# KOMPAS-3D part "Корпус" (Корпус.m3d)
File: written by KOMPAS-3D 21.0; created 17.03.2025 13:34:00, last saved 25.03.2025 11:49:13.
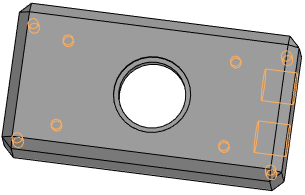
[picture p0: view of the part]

Document properties: Полное имя файла: C:\Производство\технологии\KazanTarget\эксперименты\Перспектива\Корпус платы перспективы\Корпус.m3d; Автор: fedorov478@gmail.com

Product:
- Part/product: Корпус
    Масса: 0.528769
    Форматы листов документа: A2

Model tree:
1. Эскиз:7
2. Элемент выдавливания:10
     Расстояние 1 = 106
3. Эскиз:8  (with: Элемент выдавливания:10)
4. Элемент выдавливания:11
     Расстояние 2 = 3
5. Эскиз:9  (with: Элемент выдавливания:10)
6. Отверстие:9  (with: Элемент выдавливания:10)  (labels: M4)
     Глубина выреза = 12; Диаметр отверстия = 3.24223; Угол конуса дна = 118; Расстояние 1 = 101
7. M4  (with: Элемент выдавливания:10)  (labels: M4; cil0_24705-2004 coarse)
     Длина резьбы = 10; Шаг резьбы = 0.7; Номинальный диаметр резьбы = 4
8. Фаска:3  (with: Отверстие:9)
     Угол = 45; Длина 1 = 1; Длина 2 = 1
9. Элемент выдавливания:13  (with: Элемент выдавливания:11)
     Расстояние 2 = 12
10. Массив по точкам:1
11. Экземпляр ( 2 )  (with: Отверстие:9, Эскиз:9)  (labels: M4)
12. Фаска:3
13. Экземпляр ( 1 )  (with: Отверстие:9, Эскиз:9)  (labels: M4)
14. Фаска:3
15. Экземпляр ( 3 )  (with: Отверстие:9, Эскиз:9)  (labels: M4)
16. Фаска:3
17. Эскиз:11  (with: Элемент выдавливания:13)
18. Эскиз:12  (with: Элемент выдавливания:10)
19. Отверстие:10  (with: Элемент выдавливания:10)  (labels: M12x1,5)
     Глубина выреза = 13; Диаметр отверстия = 10.3762; Угол конуса дна = 118; Расстояние 1 = 18; Расстояние 2 = 14
20. M12x1,5  (with: Элемент выдавливания:10)  (labels: M12x1,5; cil0_24705-2004 fine)
     Длина резьбы = 12; Шаг резьбы = 1.5; Номинальный диаметр резьбы = 12
21. Массив по точкам:2  (with: Экземпляр ( 1 ), Отверстие:10)  (labels: 0x0,5)
22. M12  (with: Элемент выдавливания:10)  (labels: M12x1,5; cil0_24705-2004 fine)
     Длина резьбы = 12; Шаг резьбы = 1.5; Номинальный диаметр резьбы = 12
23. Эскиз:13  (with: Элемент выдавливания:10)
24. Фаска:1  (with: Элемент выдавливания:10)
     Угол = 45; Длина 1 = 4; Длина 2 = 4
25. Эскиз:15  (with: Элемент выдавливания:13)
26. Элемент выдавливания:18
     Расстояние 2 = 3
27. Отверстие:11  (with: Элемент выдавливания:10, Фаска:1, M12)  (labels: cil0_24705-2004 coarse)
     Глубина выреза = 20; Диаметр отверстия = 25.25; Угол конуса дна = 118; Расстояние 1 = -49.9589; Расстояние 2 = -22.5594; Диаметр цековки = 29; Глубина цековки = 1.1; Длина резьбы = 30; Шаг резьбы = 1.75; Номинальный диаметр резьбы = 12
28. Отверстие:12  (with: Элемент выдавливания:13, M4)  (labels: M4; cil0_24705-2004 coarse)
     Глубина выреза = 6; Диаметр отверстия = 3.24223; Угол конуса дна = 118; Расстояние 1 = 37.8705; Расстояние 2 = 9.54877; Длина резьбы = 4; Шаг резьбы = 0.7; Номинальный диаметр резьбы = 4
29. Фаска:2  (with: Отверстие:12)
     Угол = 45; Длина 1 = 0.5; Длина 2 = 0.5
30. Массив по точкам:3  (with: Экземпляр ( 3 ), Отверстие:12)  (labels: M4)
31. Фаска:2  (with: Экземпляр ( 2 ), Отверстие:12)  (labels: M4)
32. Фаска:2  (with: Экземпляр ( 1 ), Отверстие:12)  (labels: M4)
33. Фаска:2
34. Скругление:1  (with: Элемент выдавливания:11)
     Радиус = 0.4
